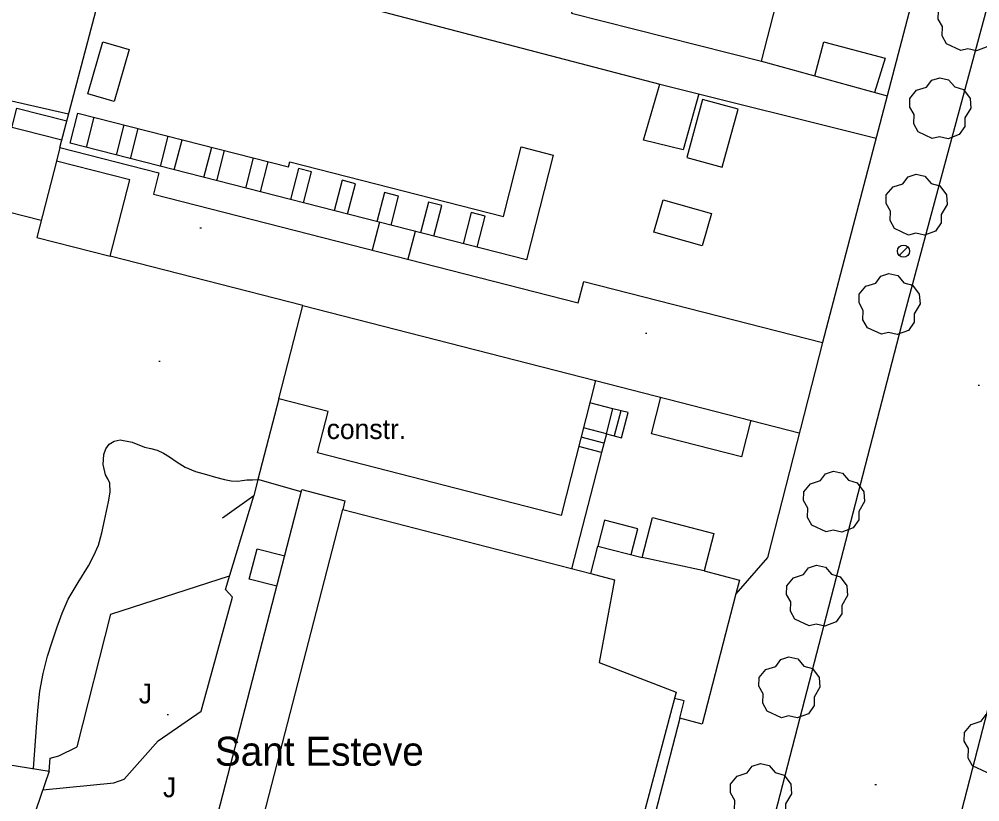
# Model space of a CAD drawing. Extents: x 431390 to 432653, y 4586754 to 4589600.
# Drawn here: x 431524.5 to 431587.4, y 4587129.9 to 4587181.2 of the extents above; entities that cross this region are included whole.
import ezdxf

# ---------------------------------------------------------------- set-up
doc = ezdxf.new("R2010")
doc.units = 0
for name, color, linetype in [('COM_06_LN', 7, 'Continuous'), ('COM_17LS_LN', 7, 'Continuous'), ('CON_01_LN', 7, 'Continuous'), ('CON_01FI_LN', 7, 'Continuous'), ('CON_04_LN', 7, 'Continuous'), ('CON_06_LN', 7, 'Continuous'), ('CON_07_LN', 7, 'Continuous'), ('CON_14LN_LN', 7, 'Continuous'), ('CON_14LS_LN', 7, 'Continuous'), ('CON_15_LN', 7, 'Continuous'), ('CON_19_LN', 7, 'Continuous'), ('CON_23_LN', 7, 'Continuous'), ('ENE_06_PT', 7, 'Continuous'), ('ENE_08_LN', 7, 'Continuous'), ('ORO_03_PT', 7, 'Continuous'), ('TOP_06_TX', 7, 'Continuous'), ('TOP_13CN_TX', 7, 'Continuous'), ('TOP_15JA_TX', 7, 'Continuous'), ('VEG_03_PT', 7, 'Continuous'), ('VEG_06_LN', 7, 'Continuous')]:
    doc.layers.add(name, color=color, linetype=linetype)

msp = doc.modelspace()

# ---------------------------------------------------------------- linework, layer by layer
at = {"layer": 'COM_06_LN'}
msp.add_lwpolyline([(431525.403, 4587132.072), (431525.63, 4587135.07), (431525.713, 4587136.107), (431525.83, 4587137.14), (431526.051, 4587138.302), (431526.34, 4587139.45), (431526.628, 4587140.385), (431526.95, 4587141.31), (431527.296, 4587142.261), (431527.69, 4587143.19), (431528.345, 4587144.284), (431529.02, 4587145.37), (431529.369, 4587146.04), (431529.67, 4587146.73), (431529.89, 4587147.532), (431530.06, 4587148.35), (431530.202, 4587148.958), (431530.32, 4587149.57), (431530.429, 4587150.194), (431530.41, 4587150.8), (431530.279, 4587151.07), (431530.14, 4587151.34), (431529.986, 4587152.004), (431530.03, 4587152.67), (431530.16, 4587153.032), (431530.37, 4587153.34), (431530.706, 4587153.536), (431531.09, 4587153.64), (431531.878, 4587153.483), (431532.68, 4587153.15), (431533.104, 4587153.061), (431533.52, 4587152.95), (431533.933, 4587152.748), (431534.33, 4587152.51), (431534.836, 4587152.161), (431535.35, 4587151.83), (431536.041, 4587151.56), (431536.76, 4587151.35), (431537.346, 4587151.174), (431537.94, 4587151.03), (431538.369, 4587150.952), (431538.8, 4587150.92), (431539.1, 4587150.955), (431539.4, 4587151), (431539.76, 4587151.019), (431540.12, 4587151.03)], dxfattribs=at)
at = {"layer": 'COM_17LS_LN'}
for points in [[(431618.835, 4587301.198), (431613.538, 4587280.567), (431609.571, 4587264.951), (431599.227, 4587226.574), (431591.042, 4587193.827), (431591.07, 4587193.733), (431589.147, 4587186.587), (431584.389, 4587168.906), (431582.46, 4587161.748), (431574.519, 4587131.009), (431565.735, 4587097.007)], [(431577.159, 4587094.055), (431585.943, 4587128.057), (431595.625, 4587165.534), (431596.369, 4587168.415), (431599.346, 4587178.693), (431601.426, 4587186.469), (431602.635, 4587190.99), (431605.953, 4587203.573), (431606.014, 4587203.593), (431610.646, 4587222.196), (431614.309, 4587236.013), (431619.276, 4587255.17), (431627.803, 4587287.858), (431630.701, 4587298.676)], [(431525.92, 4587168.011), (431522.638, 4587168.852), (431524.313, 4587175.389), (431527.598, 4587174.547)], [(431541.501, 4587156.323), (431540.12, 4587151.03)]]:
    msp.add_lwpolyline(points, dxfattribs=at)
at = {"layer": 'CON_01_LN'}
for points in [[(431587.223, 4587268.714), (431604.161, 4587264.296), (431585.37, 4587191.442), (431584.111, 4587186.635), (431581.376, 4587176.19)], [(431581.376, 4587176.19), (431577.13, 4587160.01)], [(431571.458, 4587143.533), (431569.252, 4587134.992), (431567.781, 4587135.372), (431565.206, 4587125.404), (431565.325, 4587125.486), (431565.526, 4587125.582), (431565.739, 4587125.646), (431565.959, 4587125.675), (431566.181, 4587125.67), (431566.4, 4587125.63), (431566.61, 4587125.556), (431566.805, 4587125.451), (431566.982, 4587125.316), (431567.135, 4587125.155), (431567.262, 4587124.972), (431567.358, 4587124.772), (431567.422, 4587124.556), (431567.703, 4587124.484), (431560.427, 4587096.319)]]:
    msp.add_lwpolyline(points, dxfattribs=at)
at = {"layer": 'CON_01FI_LN'}
for points in [[(431527.139, 4587172.808), (431530.919, 4587187.147), (431534.668, 4587201.371), (431563.686, 4587193.777), (431561.971, 4587186.848), (431560.672, 4587181.602), (431573.146, 4587178.458), (431575.266, 4587186.72), (431577.048, 4587193.669), (431577.015, 4587193.677), (431568.468, 4587195.972), (431587.223, 4587268.714)], [(431527.139, 4587172.808), (431533.628, 4587171.146), (431533.27, 4587169.749), (431561.13, 4587162.616), (431561.488, 4587164.014), (431577.13, 4587160.01)], [(431530.438, 4587165.677), (431531.721, 4587170.679), (431526.919, 4587171.91), (431525.637, 4587166.908), (431530.438, 4587165.677)], [(431548.231, 4587120.366), (431536.064, 4587123.509), (431543.003, 4587150.369), (431545.833, 4587149.638), (431545.683, 4587149.057), (431561.946, 4587144.856), (431562.414, 4587146.668), (431565.319, 4587145.918), (431565.995, 4587148.534), (431570.008, 4587147.497), (431569.371, 4587145.033), (431571.691, 4587144.434), (431571.458, 4587143.533)]]:
    msp.add_lwpolyline(points, dxfattribs=at)
at = {"layer": 'CON_04_LN'}
for points in [[(431530.701, 4587186.322), (431566.477, 4587176.951)], [(431531.69, 4587179.22), (431530.702, 4587175.827), (431528.978, 4587176.329), (431529.966, 4587179.722), (431531.69, 4587179.22)], [(431576.638, 4587177.496), (431577.229, 4587179.735), (431577.279, 4587179.713), (431581.236, 4587178.666), (431580.554, 4587176.416)], [(431573.146, 4587178.458), (431581.376, 4587176.19)], [(431569.035, 4587176.312), (431568, 4587172.65), (431565.41, 4587173.28), (431566.477, 4587176.951)], [(431566.477, 4587176.951), (431580.647, 4587173.411)], [(431570.568, 4587171.501), (431571.601, 4587175.303), (431569.267, 4587175.937), (431568.234, 4587172.135), (431570.568, 4587171.501)], [(431556.214, 4587168.286), (431557.377, 4587172.84), (431559.49, 4587172.3), (431557.735, 4587165.43), (431527.812, 4587173.074), (431528.319, 4587175.058), (431542.13, 4587171.53), (431542.215, 4587171.862), (431556.214, 4587168.286)], [(431566.69, 4587169.37), (431569.85, 4587168.47), (431569.248, 4587166.357), (431566.088, 4587167.257), (431566.69, 4587169.37)], [(431548.087, 4587167.895), (431547.621, 4587166.075)], [(431550.428, 4587167.297), (431549.962, 4587165.475)], [(431561.946, 4587144.856), (431563.508, 4587144.453), (431562.5, 4587139.03), (431567.54, 4587137.09), (431562.9, 4587119.56), (431539.66, 4587125.69), (431545.683, 4587149.057)], [(431569.371, 4587145.033), (431565.319, 4587145.918)], [(431567.781, 4587135.372), (431568.075, 4587136.512), (431567.431, 4587136.678)]]:
    msp.add_lwpolyline(points, dxfattribs=at)
at = {"layer": 'CON_06_LN'}
msp.add_lwpolyline([(431562.262, 4587157.518), (431559.995, 4587148.675), (431544.027, 4587152.769), (431544.726, 4587155.496), (431541.501, 4587156.323), (431543.069, 4587162.438), (431562.262, 4587157.518)], dxfattribs=at)
at = {"layer": 'CON_07_LN'}
for points in [[(431572.432, 4587154.91), (431571.82, 4587152.523), (431565.929, 4587154.034), (431566.541, 4587156.421)], [(431564.598, 4587146.104), (431565.035, 4587147.797), (431562.851, 4587148.361), (431562.414, 4587146.668)]]:
    msp.add_lwpolyline(points, dxfattribs=at)
at = {"layer": 'CON_14LN_LN'}
for points in [[(431527.139, 4587172.808), (431526.919, 4587171.91)], [(431543.069, 4587162.438), (431530.438, 4587165.677)]]:
    msp.add_lwpolyline(points, dxfattribs=at)
at = {"layer": 'CON_14LS_LN'}
for points in [[(431563.394, 4587155.67), (431561.888, 4587156.06)], [(431562.653, 4587152.803), (431560.687, 4587145.181)], [(431542.966, 4587150.226), (431540.12, 4587151.03), (431539.85, 4587149.97), (431537.8, 4587148.5)]]:
    msp.add_lwpolyline(points, dxfattribs=at)
at = {"layer": 'CON_15_LN'}
for points in [[(431501.449, 4587169.243), (431505.138, 4587161.618), (431508.644, 4587158.874), (431507.022, 4587157.621), (431516.036, 4587143.553), (431520.864, 4587132.801), (431526.443, 4587131.905), (431525.002, 4587127.695)], [(431562.262, 4587157.518), (431575.615, 4587154.094)]]:
    msp.add_lwpolyline(points, dxfattribs=at)
at = {"layer": 'CON_19_LN'}
for points in [[(431520.299, 4587176.697), (431527.717, 4587175.001)], [(431522.185, 4587174.591), (431527.269, 4587173.3)], [(431577.13, 4587160.01), (431573.521, 4587145.914), (431571.458, 4587143.533)], [(431526.023, 4587130.679), (431530.68, 4587131.14), (431531.35, 4587131.39), (431533.59, 4587133.9), (431536.41, 4587135.85), (431538.46, 4587143.32), (431537.99, 4587143.82), (431539.85, 4587149.97)], [(431526.443, 4587131.905), (431526.514, 4587132.755), (431527.08, 4587132.92), (431528.27, 4587133.51), (431530.48, 4587142.2), (431538.259, 4587144.71)]]:
    msp.add_lwpolyline(points, dxfattribs=at)
at = {"layer": 'CON_23_LN'}
for points in [[(431562.968, 4587154.024), (431563.394, 4587155.67)], [(431562.968, 4587154.024), (431563.962, 4587153.767), (431564.388, 4587155.413), (431563.394, 4587155.67)], [(431563.908, 4587155.537), (431563.482, 4587153.891)], [(431562.968, 4587154.024), (431561.466, 4587154.412)], [(431562.968, 4587154.024), (431562.653, 4587152.803)], [(431562.811, 4587153.414), (431561.309, 4587153.8)], [(431562.653, 4587152.803), (431561.153, 4587153.19)]]:
    msp.add_lwpolyline(points, dxfattribs=at)
at = {"layer": 'ENE_06_PT'}
msp.add_line((431582.732, 4587166.282), (431582.166, 4587165.716), dxfattribs=at)
msp.add_circle((431582.449, 4587165.999), 0.4, dxfattribs=at)
at = {"layer": 'ENE_08_LN'}
for points in [[(431528.887, 4587172.799), (431529.393, 4587174.784)], [(431530.851, 4587172.298), (431531.358, 4587174.282)], [(431531.768, 4587172.063), (431532.275, 4587174.047)], [(431533.742, 4587171.559), (431534.249, 4587173.543)], [(431534.644, 4587171.329), (431535.151, 4587173.313)], [(431536.59, 4587170.832), (431537.097, 4587172.816)], [(431537.429, 4587170.617), (431537.936, 4587172.601)], [(431539.323, 4587170.133), (431539.83, 4587172.117)], [(431540.293, 4587169.886), (431540.8, 4587171.87)], [(431543.123, 4587169.163), (431543.642, 4587171.194), (431542.777, 4587171.415), (431542.258, 4587169.384)], [(431546.009, 4587168.426), (431546.52, 4587170.425), (431545.642, 4587170.649), (431545.131, 4587168.65)], [(431548.855, 4587167.698), (431549.343, 4587169.607), (431548.419, 4587169.843), (431547.931, 4587167.934)], [(431551.663, 4587166.981), (431552.179, 4587169.002), (431551.309, 4587169.224), (431550.793, 4587167.203)], [(431554.497, 4587166.257), (431555.019, 4587168.302), (431554.102, 4587168.536), (431553.58, 4587166.491)]]:
    msp.add_lwpolyline(points, dxfattribs=at)
at = {"layer": 'ORO_03_PT'}
for p, q in [((431536.32, 4587167.54), (431536.42, 4587167.54)), ((431565.53, 4587160.63), (431565.63, 4587160.63)), ((431533.62, 4587158.79), (431533.72, 4587158.79)), ((431587.334, 4587157.222), (431587.434, 4587157.222)), ((431534.17, 4587135.62), (431534.27, 4587135.62)), ((431580.568, 4587131.033), (431580.668, 4587131.033))]:
    msp.add_line(p, q, dxfattribs=at)
at = {"layer": 'VEG_03_PT'}
for points in [[(431586.201, 4587179.162), (431585.274, 4587179.597), (431584.986, 4587180.118), (431585.009, 4587180.732), (431584.727, 4587181.224), (431584.735, 4587181.787), (431585.176, 4587182.322), (431585.829, 4587182.526), (431586.164, 4587182.977), (431586.69, 4587183.147), (431587.27, 4587183.014), (431587.67, 4587182.548), (431588.244, 4587182.378), (431588.678, 4587181.795), (431588.727, 4587181.153), (431588.344, 4587180.506), (431588.344, 4587179.956), (431587.972, 4587179.422), (431587.233, 4587179.147), (431586.668, 4587179.275), (431586.201, 4587179.162)], [(431584.334, 4587173.391), (431583.407, 4587173.826), (431583.119, 4587174.347), (431583.142, 4587174.961), (431582.86, 4587175.453), (431582.868, 4587176.016), (431583.309, 4587176.551), (431583.962, 4587176.755), (431584.297, 4587177.206), (431584.823, 4587177.376), (431585.403, 4587177.243), (431585.803, 4587176.777), (431586.377, 4587176.607), (431586.811, 4587176.024), (431586.86, 4587175.382), (431586.477, 4587174.735), (431586.477, 4587174.185), (431586.105, 4587173.651), (431585.366, 4587173.376), (431584.801, 4587173.504), (431584.334, 4587173.391)], [(431582.784, 4587167.061), (431581.857, 4587167.496), (431581.569, 4587168.017), (431581.592, 4587168.631), (431581.31, 4587169.123), (431581.318, 4587169.686), (431581.759, 4587170.221), (431582.412, 4587170.425), (431582.747, 4587170.876), (431583.273, 4587171.046), (431583.853, 4587170.913), (431584.253, 4587170.447), (431584.827, 4587170.277), (431585.261, 4587169.694), (431585.31, 4587169.052), (431584.927, 4587168.405), (431584.927, 4587167.855), (431584.555, 4587167.321), (431583.816, 4587167.046), (431583.251, 4587167.174), (431582.784, 4587167.061)], [(431581.004, 4587160.551), (431580.077, 4587160.986), (431579.789, 4587161.507), (431579.812, 4587162.121), (431579.53, 4587162.613), (431579.538, 4587163.176), (431579.979, 4587163.711), (431580.632, 4587163.915), (431580.967, 4587164.366), (431581.493, 4587164.536), (431582.073, 4587164.403), (431582.473, 4587163.937), (431583.047, 4587163.767), (431583.481, 4587163.184), (431583.53, 4587162.542), (431583.147, 4587161.895), (431583.147, 4587161.345), (431582.775, 4587160.811), (431582.036, 4587160.536), (431581.471, 4587160.664), (431581.004, 4587160.551)], [(431577.374, 4587147.591), (431576.447, 4587148.026), (431576.159, 4587148.547), (431576.182, 4587149.161), (431575.9, 4587149.653), (431575.908, 4587150.216), (431576.349, 4587150.751), (431577.002, 4587150.955), (431577.337, 4587151.406), (431577.863, 4587151.576), (431578.443, 4587151.443), (431578.843, 4587150.977), (431579.417, 4587150.807), (431579.851, 4587150.224), (431579.9, 4587149.582), (431579.517, 4587148.935), (431579.517, 4587148.385), (431579.145, 4587147.851), (431578.406, 4587147.576), (431577.841, 4587147.704), (431577.374, 4587147.591)], [(431576.254, 4587141.431), (431575.327, 4587141.866), (431575.039, 4587142.387), (431575.062, 4587143.001), (431574.78, 4587143.493), (431574.788, 4587144.056), (431575.229, 4587144.591), (431575.882, 4587144.795), (431576.217, 4587145.246), (431576.743, 4587145.416), (431577.323, 4587145.283), (431577.723, 4587144.817), (431578.297, 4587144.647), (431578.731, 4587144.064), (431578.78, 4587143.422), (431578.397, 4587142.775), (431578.397, 4587142.225), (431578.025, 4587141.691), (431577.286, 4587141.416), (431576.721, 4587141.544), (431576.254, 4587141.431)], [(431574.444, 4587135.411), (431573.517, 4587135.846), (431573.229, 4587136.367), (431573.252, 4587136.981), (431572.97, 4587137.473), (431572.978, 4587138.036), (431573.419, 4587138.571), (431574.072, 4587138.775), (431574.407, 4587139.226), (431574.933, 4587139.396), (431575.513, 4587139.263), (431575.913, 4587138.797), (431576.487, 4587138.627), (431576.921, 4587138.044), (431576.97, 4587137.402), (431576.587, 4587136.755), (431576.587, 4587136.205), (431576.215, 4587135.671), (431575.476, 4587135.396), (431574.911, 4587135.524), (431574.444, 4587135.411)], [(431587.904, 4587131.811), (431586.977, 4587132.246), (431586.689, 4587132.767), (431586.712, 4587133.381), (431586.43, 4587133.873), (431586.438, 4587134.436), (431586.879, 4587134.971), (431587.532, 4587135.175), (431587.867, 4587135.626), (431588.393, 4587135.796), (431588.973, 4587135.663), (431589.373, 4587135.197), (431589.947, 4587135.027), (431590.381, 4587134.444), (431590.43, 4587133.802), (431590.047, 4587133.155), (431590.047, 4587132.605), (431589.675, 4587132.071), (431588.936, 4587131.796), (431588.371, 4587131.924), (431587.904, 4587131.811)], [(431572.574, 4587128.421), (431571.647, 4587128.856), (431571.359, 4587129.377), (431571.382, 4587129.991), (431571.1, 4587130.483), (431571.108, 4587131.046), (431571.549, 4587131.581), (431572.202, 4587131.785), (431572.537, 4587132.236), (431573.063, 4587132.406), (431573.643, 4587132.273), (431574.043, 4587131.807), (431574.617, 4587131.637), (431575.051, 4587131.054), (431575.1, 4587130.412), (431574.717, 4587129.765), (431574.717, 4587129.215), (431574.345, 4587128.681), (431573.606, 4587128.406), (431573.041, 4587128.534), (431572.574, 4587128.421)]]:
    msp.add_lwpolyline(points, dxfattribs=at)
at = {"layer": 'VEG_06_LN'}
msp.add_lwpolyline([(431541.366, 4587144.033), (431539.559, 4587144.5), (431540.074, 4587146.492), (431541.881, 4587146.025)], dxfattribs=at)

# ---------------------------------------------------------------- texts
at = {"layer": 'TOP_06_TX'}
msp.add_text('Sant Esteve', height=1.9, dxfattribs=at).set_placement((431537.301, 4587132.26))
at = {"layer": 'TOP_13CN_TX'}
msp.add_text('constr.', height=1.3, dxfattribs=at).set_placement((431544.63, 4587153.685))
at = {"layer": 'TOP_15JA_TX'}
for p in [(431532.32, 4587136.345), (431533.9, 4587130.195)]:
    msp.add_text('J', height=1.3, dxfattribs=at).set_placement(p)

doc.saveas('drawing.dxf')
